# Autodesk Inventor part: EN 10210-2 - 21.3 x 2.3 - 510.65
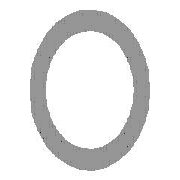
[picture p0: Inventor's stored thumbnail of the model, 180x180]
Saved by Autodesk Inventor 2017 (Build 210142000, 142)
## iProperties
Created: 2016-02
Part Number: EN 10210-2 - 21.3 x 2.3 - 510.65
Material: Steel, Mild
Description: Pipe
Document SubType Name: Modeling
Standard: DIN
Designer: iusti
Standard Revision: 2006-07
Standards Organization: DIN
Language: en-US
Size Designation: 21.3 x 2.3
Categories: <MemberInstance><Categories><Category DisplayName="Structural Shapes" InternalName="089c4875-fa83-4c05-b084-43b9cc11f5ed" Mnemonic="GRDR"><CategoryParameter Dis
Stock Number: 21.3 x 2.3
Density: 7.85 g/cm^3
Appearance: Semi-Polished
IsCustomPart: 1
_CCFamilyMember: 1
_CCFamilyDisplayName: DIN EN 10210-2 - Pipe
_FrameMemberDoc: Frame Member File
_Version: 15.0.0
_GetPNFromCC: 1
Author: iusti
G_L: 507.531 mm
G_W: 21.300 mm
G_H: 21.300 mm
+80B2A45B-F442-4791-9C48-37951358E670+CUTDETAIL1: Miter 45.00 deg
+4C4787AB-0BAD-477D-B088-ADA6A635DAD2+CUTDETAIL2: Miter 45.00 deg
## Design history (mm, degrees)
node "Start plane"
node "End plane"
sketch "Sketch"
  geometry: C1 r 8.35 at (0, 0); C2 r 10.65 at (0, 0); 2 further points
  constraints: 3 coincident, 2 centre point
  dimensions: "d0" = 21.3 diameter of C2 (= G_H); "d1" = 2.3 radial gap between concentric circles of C2 C1 (= G_T)
extrude "Body" new body sketch "Sketch" stored distance "d2" = 507.53069 (= G_L); taper "d3" = 0 deg
node "Driven Length"
  sketch "Sketch3"
    geometry: L1 (0, 0)-(10, 0) reference
    constraints: 2 end point, 1 horizontal
  workplane "Work Plane3"
  sketch "Sketch4"
    geometry: L1 (-2, 0)-(12, 0) reference; L2 (-2, 510.65)-(12, 510.65) reference
    dimensions: "d7" = 510.65 distance between parallel lines of L1 L2 (derived)
workplane "Work Plane4"
split "Split1"
workplane "Work Plane5"
split "Split2"
body "Solid1"
other parameters: "G_H" = 21.3 [user parameter; used in 1 equation term], "G_T" = 2.3 [user parameter; used in 1 equation term], "G_L" = 507.53069 [user parameter; used in 1 equation term], "G_OFFSET_START" = 0 [user parameter; used in 1 equation term], "G_OFFSET_END" = 10.65 [user parameter; used in 1 equation term], "d4" = 0 (computed from G_OFFSET_START), "d5" = 510.65 (= G_OFFSET_END + B_L), "d6" = 90 deg
